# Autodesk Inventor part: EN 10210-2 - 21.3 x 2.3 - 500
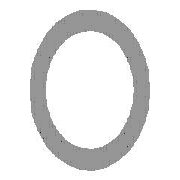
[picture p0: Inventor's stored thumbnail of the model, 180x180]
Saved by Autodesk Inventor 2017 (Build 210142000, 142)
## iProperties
Created: 2016-02
Part Number: EN 10210-2 - 21.3 x 2.3 - 500
Material: Steel, Mild
Description: Pipe
Document SubType Name: Modeling
Standard: DIN
Designer: iusti
Standard Revision: 2006-07
Standards Organization: DIN
Language: en-US
Size Designation: 21.3 x 2.3
Categories: <MemberInstance><Categories><Category DisplayName="Structural Shapes" InternalName="089c4875-fa83-4c05-b084-43b9cc11f5ed" Mnemonic="GRDR"><CategoryParameter Dis
Stock Number: 21.3 x 2.3
Density: 7.85 g/cm^3
Appearance: Semi-Polished
IsCustomPart: 1
_CCFamilyMember: 1
_CCFamilyDisplayName: DIN EN 10210-2 - Pipe
_FrameMemberDoc: Frame Member File
_Version: 15.0.0
_GetPNFromCC: 1
Author: iusti
G_L: 500.000 mm
G_W: 21.300 mm
G_H: 21.300 mm
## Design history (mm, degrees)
node "Start plane"
node "End plane"
sketch "Sketch"
  geometry: C1 r 8.35 at (0, 0); C2 r 10.65 at (0, 0); 2 further points
  constraints: 3 coincident, 2 centre point
  dimensions: "d0" = 21.3 diameter of C2 (= G_H); "d1" = 2.3 radial gap between concentric circles of C2 C1 (= G_T)
extrude "Body" new body sketch "Sketch" stored distance "d2" = 500 (= G_L); taper "d3" = 0 deg
node "Driven Length"
  sketch "Sketch3"
    geometry: L1 (0, 0)-(10, 0) reference
    constraints: 2 end point, 1 horizontal
  workplane "Work Plane3"
  sketch "Sketch4"
    geometry: L1 (-2, 0)-(12, 0) reference; L2 (-2, 500)-(12, 500) reference
    dimensions: "d7" = 500 distance between parallel lines of L1 L2 (derived)
body "Solid1"
other parameters: "G_H" = 21.3 [user parameter; used in 1 equation term], "G_T" = 2.3 [user parameter; used in 1 equation term], "G_L" = 500 (= d7) [user parameter; used in 1 equation term], "G_OFFSET_START" = 0 [user parameter; used in 1 equation term], "G_OFFSET_END" = 0 [user parameter; used in 1 equation term], "d4" = 0 (computed from G_OFFSET_START), "d6" = 90 deg
